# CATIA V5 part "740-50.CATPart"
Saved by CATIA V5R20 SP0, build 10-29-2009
Part number: 740-50
Bounding box of the stored display mesh (mm): x -39.9 to 39.9, y -37 to 39.9, z -47 to 18
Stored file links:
  C:\Users\Utente\Desktop\IO LAVORO\3D X SITO CF\X SITO\740\740-50.CATPart
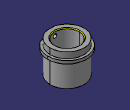
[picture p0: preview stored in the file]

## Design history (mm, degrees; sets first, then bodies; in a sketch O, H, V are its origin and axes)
Set1
  DatumSurface1 to DatumSurface35 "740-50"
Body1 (main body)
